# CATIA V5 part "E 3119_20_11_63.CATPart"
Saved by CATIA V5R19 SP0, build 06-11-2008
Nomenclature: E 3119_20_11_63
Description: PART-E 3119_20_11_63-DESC
Property "Hersteller": "Meusburger"
Property "Material": "2.0598 180 HB / Graphit _ graphite"
Property "Bestellnummer": "E 3119/20/11/63"
Property "Teilenummer": "E 3119/20/11/63"
Property "Beschreibung": "Führungsleiste einseitig, wartungsfrei, mit Schraubenbohrungen _ One-sided self lubricating guiding rail, with screw holes"
Material "Brass": density 8216 kg/m3, Young's modulus 1.31e+11 Pa, Poisson ratio 0.35, thermal expansion 1.67e-05 1/K
Bounding box of the stored display mesh (mm): x 0 to 63, y -5 to 15, z 0 to 20
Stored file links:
  G:\UTB\Kombinované\Bakalářská práce\Catia\FORMA\E 3119_20_11_63.CATPart
  D:\Aplikace\CATIA\Nová složka\win_b64\startup\materials\Catalog.CATMaterial
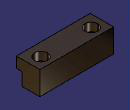
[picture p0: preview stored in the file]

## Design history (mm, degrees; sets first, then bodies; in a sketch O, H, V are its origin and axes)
Body1 "E 3119_20_11_63" (main body)
  Solid1: solid without history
